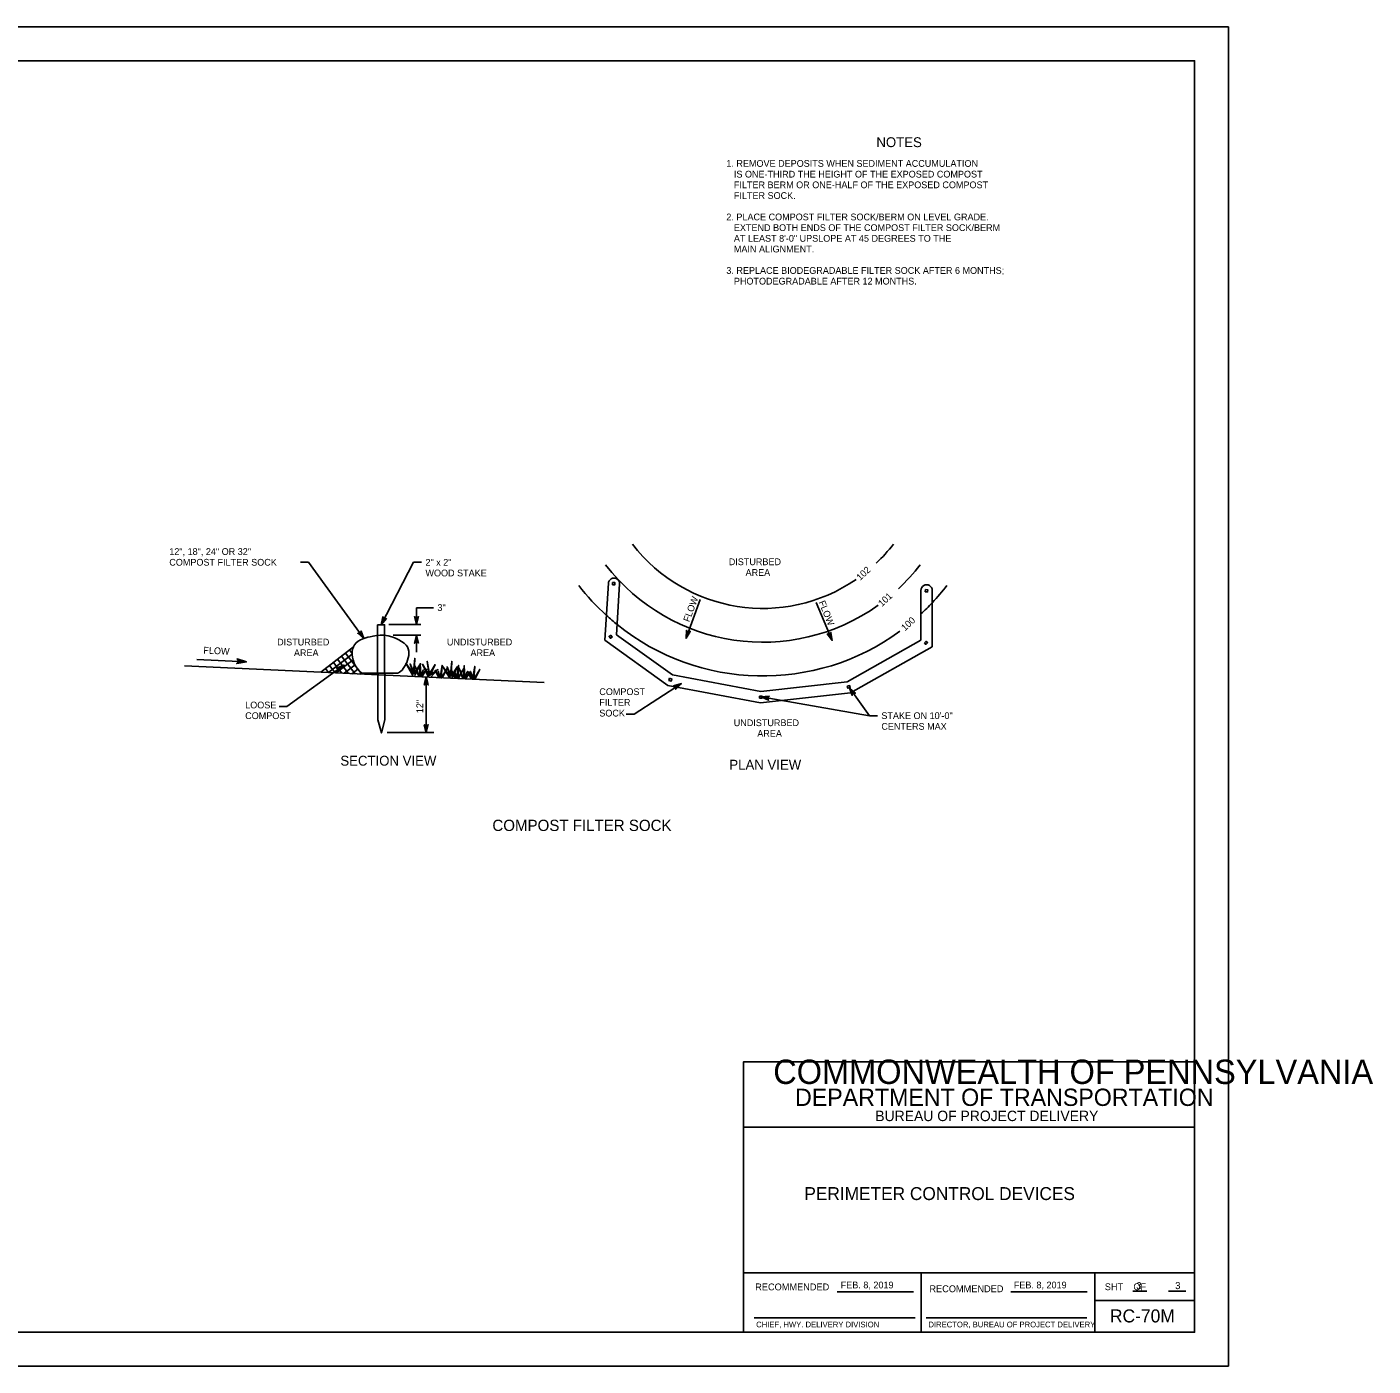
# Model space of a CAD drawing. Extents: x 636462 to 639049, y 299944 to 300538.
# Drawn here: x 638452 to 639049, y 299944 to 300538 of the extents above; entities that cross this region are included whole.
import ezdxf

# ---------------------------------------------------------------- set-up
doc = ezdxf.new("R2010")
doc.units = 0
for name, color, linetype in [('1', 7, 'Continuous'), ('Default', 7, 'Continuous'), ('PLT-BNDY', 7, 'Continuous')]:
    doc.layers.add(name, color=color, linetype=linetype)

msp = doc.modelspace()

# ---------------------------------------------------------------- linework, layer by layer
at = {"layer": '1'}
for p, q in [((638811.38, 299977.44), (638845.27, 299977.44)), ((638888.38, 299977.44), (638922.25, 299977.44)), ((638942.54, 299977.66), (638948.68, 299977.66)), ((638958.35, 299977.66), (638965.99, 299977.66)), ((638774.68, 299965.87), (638845.93, 299965.87)), ((638850.85, 299965.87), (638922.19, 299965.87))]:
    msp.add_line(p, q, dxfattribs=at)
msp.add_lwpolyline([(638969.91, 299959.45), (638969.91, 300523.45), (638183.91, 300523.45), (638183.91, 299959.45), (638969.91, 299959.45), (638969.91, 299985.81), (638769.91, 299985.81), (638769.91, 300050.49), (638969.91, 300050.49), (638969.91, 300079.45), (638769.91, 300079.45), (638769.91, 299959.45), (638848.72, 299959.45), (638848.72, 299985.81), (638848.72, 299959.45), (638925.72, 299959.45), (638925.72, 299985.81), (638925.72, 299973.49), (638969.91, 299973.49)], dxfattribs=at)
at = {"layer": 'Default'}
for p, q in [((638573.46, 300301.02), (638576.96, 300301.02)), ((638601.59, 300267.12), (638576.96, 300301.02)), ((638609.18, 300273.31), (638623.61, 300300.97)), ((638627.11, 300300.97), (638623.61, 300300.97)), ((638708.43, 300266.42), (638709.98, 300291.78)), ((638713.58, 300268.87), (638714.97, 300291.47)), ((638848.57, 300266.44), (638848.57, 300288.49)), ((638853.56, 300263.52), (638853.56, 300288.49)), ((638624.93, 300280.74), (638632.47, 300280.74)), ((638624.93, 300273.37), (638624.93, 300280.74)), ((638744.39, 300267.26), (638750.68, 300284.41)), ((638809.2, 300266.31), (638802.08, 300283.14)), ((638624.93, 300268.6), (638624.93, 300261.14)), ((638596.9, 300263.45), (638582.41, 300252.21)), ((638549.44, 300256.82), (638527.54, 300257.83)), ((638596.41, 300260.22), (638585.88, 300252.05)), ((638588.05, 300256.58), (638591.77, 300251.78)), ((638596.82, 300257.69), (638589.34, 300251.89)), ((638589.82, 300257.96), (638594.72, 300251.65)), ((638591.6, 300259.33), (638597.67, 300251.51)), ((638593.38, 300260.71), (638600.62, 300251.37)), ((638595.15, 300262.09), (638596.42, 300260.46)), ((638592.7, 300255.42), (638567.45, 300236.99)), ((638582.72, 300252.45), (638582.92, 300252.19)), ((638584.49, 300253.82), (638585.87, 300252.05)), ((638586.27, 300255.2), (638588.82, 300251.92)), ((638597.64, 300255.48), (638592.81, 300251.73)), ((638598.82, 300253.56), (638596.27, 300251.57)), ((638600.51, 300252.01), (638599.73, 300251.42)), ((638629.2, 300250.06), (638629.2, 300225.46)), ((638742.33, 300247.21), (638721.38, 300233.63)), ((638816.86, 300245.33), (638825.78, 300232.94)), ((638777.74, 300241.26), (638825.78, 300232.94)), ((638563.95, 300236.99), (638567.45, 300236.99)), ((638717.88, 300233.63), (638721.38, 300233.63)), ((638829.27, 300232.94), (638825.78, 300232.94))]:
    msp.add_line(p, q, dxfattribs=at)
for points in [[(638711.84, 300292), (638712.9, 300291.96), (638712.87, 300291.02), (638711.81, 300291.05)], [(638850.51, 300288.84), (638851.56, 300288.81), (638851.53, 300287.86), (638850.48, 300287.9)], [(638711.04, 300268.68), (638711.66, 300267.83), (638710.89, 300267.27), (638710.27, 300268.13)], [(638850.08, 300265.28), (638850.87, 300265.99), (638851.5, 300265.29), (638850.72, 300264.58)], [(638737.12, 300249.51), (638738.13, 300249.18), (638737.83, 300248.29), (638736.83, 300248.61)], [(638815.9, 300245.98), (638816.9, 300246.31), (638817.2, 300245.41), (638816.21, 300245.08)], [(638777.03, 300241.66), (638778.08, 300241.64), (638778.06, 300240.7), (638777.01, 300240.72)]]:
    msp.add_lwpolyline(points, close=True, dxfattribs=at)
for points in [[(638611.21, 300275.9), (638611.53, 300276.04), (638609.18, 300273.31), (638611.21, 300275.9), (638610.79, 300275.9), (638609.18, 300273.31), (638610.32, 300276.13), (638610.07, 300276.46), (638609.18, 300273.31), (638609.97, 300276.83), (638610.07, 300276.46)], [(638625.56, 300276.6), (638625.79, 300276.87), (638624.93, 300273.37), (638625.56, 300276.6), (638625.19, 300276.41), (638624.93, 300273.37), (638624.67, 300276.4), (638624.29, 300276.58), (638624.93, 300273.37), (638624.04, 300276.87), (638624.29, 300276.58)], [(638600.1, 300266.54), (638600.83, 300266.82), (638601.59, 300267.12), (638602.42, 300267.41), (638603.36, 300267.7), (638604.42, 300267.98), (638605.65, 300268.24), (638607.09, 300268.46), (638608.76, 300268.65), (638608.76, 300268.65), (638610.52, 300268.61), (638612.26, 300268.35), (638613.94, 300267.91), (638615.53, 300267.33), (638616.99, 300266.63), (638618.29, 300265.86), (638619.39, 300265.04), (638620.25, 300264.23), (638620.25, 300264.23), (638620.83, 300263.43), (638621.23, 300262.54), (638621.44, 300261.59), (638621.5, 300260.59), (638621.43, 300259.57), (638621.23, 300258.54), (638620.93, 300257.51), (638620.54, 300256.52), (638620.09, 300255.58), (638619.58, 300254.69), (638619.04, 300253.9), (638618.5, 300253.2), (638617.95, 300252.63), (638617.42, 300252.2), (638616.93, 300251.92), (638616.5, 300251.82), (638616.5, 300251.82), (638600.82, 300251.82), (638600.82, 300251.82), (638600.1, 300252.26), (638599.4, 300252.88), (638598.74, 300253.65), (638598.14, 300254.55), (638597.6, 300255.56), (638597.15, 300256.63), (638596.79, 300257.77), (638596.54, 300258.94), (638596.41, 300260.11), (638596.42, 300261.27), (638596.58, 300262.39), (638596.9, 300263.45), (638597.4, 300264.41), (638598.09, 300265.26), (638598.99, 300265.98), (638600.1, 300266.54)], [(638600.26, 300270.13), (638600.29, 300270.48), (638601.59, 300267.12), (638600.26, 300270.13), (638600.07, 300269.75), (638601.59, 300267.12), (638599.64, 300269.45), (638599.23, 300269.38), (638601.59, 300267.12), (638598.86, 300269.47), (638599.23, 300269.38)], [(638607.62, 300273.31), (638610.75, 300273.31), (638610.84, 300231.03), (638609.3, 300225.31), (638607.72, 300231.03), (638607.62, 300273.31)], [(638612.61, 300273.37), (638626.78, 300273.37)], [(638614.49, 300268.59), (638626.78, 300268.59)], [(638624.29, 300265.37), (638624.07, 300265.1), (638624.93, 300268.6), (638624.29, 300265.37), (638624.66, 300265.57), (638624.93, 300268.6), (638625.19, 300265.57), (638625.56, 300265.39), (638624.93, 300268.6), (638625.81, 300265.11), (638625.56, 300265.39)], [(638713.58, 300268.87), (638738.38, 300251.09), (638777.59, 300243.68), (638815.83, 300247.97), (638848.57, 300266.44)], [(638746.01, 300270.13), (638746.3, 300270.32), (638744.39, 300267.26), (638746.01, 300270.13), (638745.59, 300270.06), (638744.39, 300267.26), (638745.09, 300270.22), (638744.79, 300270.51), (638744.39, 300267.26), (638744.64, 300270.85), (638744.79, 300270.51)], [(638808.54, 300269.54), (638808.64, 300269.88), (638809.2, 300266.31), (638808.54, 300269.54), (638808.27, 300269.22), (638809.2, 300266.31), (638807.79, 300269.01), (638807.37, 300269.03), (638809.2, 300266.31), (638807.03, 300269.2), (638807.37, 300269.03)], [(638708.43, 300266.42), (638736.37, 300246.38), (638777.4, 300238.64), (638817.4, 300243.12), (638853.56, 300263.52)], [(638545.62, 300257.85), (638545.31, 300258.14), (638549.44, 300256.82), (638545.62, 300257.85), (638545.82, 300257.38), (638549.44, 300256.82), (638545.79, 300256.76), (638545.54, 300256.32), (638549.44, 300256.82), (638545.18, 300256.04), (638545.54, 300256.32)], [(638624.21, 300250.74), (638626.73, 300255.99), (638623.89, 300251.78), (638624.1, 300258.41), (638623.54, 300252.33), (638622.04, 300255.92), (638623.5, 300251.46), (638620.1, 300256.19), (638623.25, 300250.8)], [(638631.15, 300249.91), (638634.36, 300253.42), (638630.93, 300250.98), (638633.1, 300255.6), (638630.64, 300251.56), (638629.68, 300257.09), (638630.51, 300250.7), (638627.58, 300255.73), (638630.2, 300250.07)], [(638640.6, 300249.45), (638643.13, 300254.69), (638640.29, 300250.49), (638640.49, 300257.12), (638639.94, 300251.04), (638638.44, 300254.63), (638639.89, 300250.17), (638636.49, 300254.9), (638639.65, 300249.51)], [(638521.95, 300254.99), (638681.43, 300247.66)], [(638589.73, 300254), (638589.38, 300254.02), (638592.7, 300255.42), (638589.73, 300254), (638590.11, 300253.82), (638592.7, 300255.42), (638590.42, 300253.4), (638590.5, 300252.99), (638592.7, 300255.42), (638590.43, 300252.62), (638590.5, 300252.99)], [(638625.89, 300250.36), (638624.14, 300255), (638626.26, 300250.4), (638626.56, 300256.05), (638626.79, 300250.4), (638627.9, 300253.18), (638627.03, 300250.44), (638629.35, 300253.45), (638627.27, 300250.23)], [(638636.27, 300249.69), (638638.52, 300253.94), (638635.84, 300249.65), (638636.26, 300255.29), (638635.32, 300249.72), (638634.57, 300252.62), (638635.08, 300249.78), (638633.17, 300253.07), (638634.74, 300249.76)], [(638643.58, 300249.62), (638645.84, 300253.88), (638643.15, 300249.59), (638643.57, 300255.23), (638642.63, 300249.65), (638641.88, 300252.55), (638642.4, 300249.72), (638640.48, 300253.01), (638642.06, 300249.7)], [(638645.39, 300249.5), (638643.63, 300254.14), (638645.75, 300249.55), (638646.05, 300255.19), (638646.28, 300249.54), (638647.39, 300252.32), (638646.52, 300249.58), (638648.84, 300252.6), (638646.76, 300249.37)], [(638650.71, 300249.19), (638652.96, 300253.45), (638650.27, 300249.16), (638650.7, 300254.8), (638649.75, 300249.22), (638649.01, 300252.12), (638649.52, 300249.29), (638647.6, 300252.58), (638649.18, 300249.27)], [(638628.56, 300246.83), (638628.34, 300246.56), (638629.2, 300250.06), (638628.56, 300246.83), (638628.93, 300247.03), (638629.2, 300250.06), (638629.46, 300247.03), (638629.83, 300246.85), (638629.2, 300250.06), (638630.08, 300246.57), (638629.83, 300246.85)], [(638739.24, 300246.08), (638738.9, 300246.13), (638742.33, 300247.21), (638739.24, 300246.08), (638739.6, 300245.86), (638742.33, 300247.21), (638739.88, 300245.42), (638739.92, 300245), (638742.33, 300247.21), (638739.81, 300244.64), (638739.92, 300245)], [(638818.13, 300242.29), (638818.09, 300241.94), (638816.86, 300245.33), (638818.13, 300242.29), (638818.33, 300242.66), (638816.86, 300245.33), (638818.76, 300242.96), (638819.17, 300243.02), (638816.86, 300245.33), (638819.54, 300242.92), (638819.17, 300243.02)], [(638780.81, 300240.08), (638781.04, 300239.81), (638777.74, 300241.26), (638780.81, 300240.08), (638780.68, 300240.48), (638777.74, 300241.26), (638780.77, 300241), (638781.01, 300241.34), (638777.74, 300241.26), (638781.33, 300241.54), (638781.01, 300241.34)], [(638629.83, 300228.69), (638630.06, 300228.96), (638629.2, 300225.46), (638629.83, 300228.69), (638629.46, 300228.49), (638629.2, 300225.46), (638628.94, 300228.49), (638628.56, 300228.67), (638629.2, 300225.46), (638628.31, 300228.95), (638628.56, 300228.67)], [(638611.86, 300225.46), (638632.64, 300225.46)]]:
    msp.add_lwpolyline(points, dxfattribs=at)
for centre, radius, start, end in [((638778.47, 300353.57), 73.04, 217.62146, 304.47323), ((638778.47, 300353.57), 73.04, 313.52077, 322.37854), ((638778.47, 300353.57), 88.03, 217.62146, 305.53768), ((638778.47, 300353.57), 88.03, 313.0326, 322.37854), ((638712.47, 300291.47), 2.5, 359.99938, 180.00062), ((638778.47, 300353.57), 103.02, 217.62146, 227.67001), ((638851.07, 300288.49), 2.5, 359.99938, 180.00062), ((638778.47, 300353.57), 103.02, 316.79278, 322.37854), ((638778.47, 300353.57), 103.02, 312.87336, 316.79278), ((638778.47, 300353.57), 103.02, 227.67001, 231.15361), ((638778.47, 300353.57), 103.02, 231.15361, 306.13463)]:
    msp.add_arc(centre, radius, start, end, dxfattribs=at)
at = {"layer": 'PLT-BNDY'}
msp.add_lwpolyline([(638143.91, 300538.45), (638984.91, 300538.45), (638984.91, 299944.45), (638143.91, 299944.45)], close=True, dxfattribs=at)

# ---------------------------------------------------------------- texts
at = {"layer": '1'}
for s, height, p in [('COMMONWEALTH OF PENNSYLVANIA', 10.7834, (638783.07, 300069.59)), ('DEPARTMENT OF TRANSPORTATION', 7.6843, (638792.75, 300059.84)), ('BUREAU OF PROJECT DELIVERY', 4.6221, (638828.32, 300053.11)), ('RECOMMENDED', 3.048, (638775.08, 299978.04)), ('APPROVED', 0.0192, (638812.94, 299977.38)), ('APPROVED', 0.0192, (638812.94, 299977.38)), ('APPROVED', 0.0192, (638812.94, 299977.38)), ('APPROVED', 0.0192, (638812.94, 299977.38)), ('FEB. 8, 2019', 3, (638812.99, 299978.92)), ('RECOMMENDED', 3.048, (638852.32, 299977.21)), ('FEB. 8, 2019', 3, (638889.74, 299978.92)), ('SHT    OF', 3.048, (638930.08, 299978.12)), ('3', 3.13, (638944.05, 299978.54)), ('3', 3.13, (638961.28, 299978.59)), ('CHIEF, HWY. DELIVERY DIVISION', 2.54, (638775.5, 299961.62)), ('DIRECTOR, BUREAU OF PROJECT DELIVERY', 2.54, (638851.88, 299961.62))]:
    msp.add_text(s, height=height, dxfattribs=at).set_placement(p)
at = {"layer": 'Default'}
for s, height, p in [('NOTES', 4.372, (638828.81, 300485.13)), ('   AT LEAST 8\'-0" UPSLOPE AT 45 DEGREES TO THE', 2.998, (638762.28, 300443.16)), ('12", 18", 24" OR 32"', 2.998, (638515.28, 300304.24)), ('COMPOST FILTER SOCK', 2.998, (638515.28, 300299.49)), ('2" x 2" ', 2.998, (638628.86, 300299.47)), ('DISTURBED', 2.998, (638763.35, 300299.7)), ('WOOD STAKE', 2.998, (638628.86, 300294.73)), ('AREA', 2.998, (638770.8, 300294.95)), ('3"', 2.998, (638634.16, 300279.38)), ('DISTURBED', 2.998, (638563.09, 300264.09)), ('UNDISTURBED', 2.998, (638638.38, 300264.09)), ('AREA', 2.998, (638570.54, 300259.34)), ('AREA', 2.998, (638648.83, 300259.34)), ('COMPOST', 2.998, (638705.95, 300242.08)), ('LOOSE ', 2.998, (638548.93, 300236.17)), ('FILTER', 2.998, (638705.95, 300237.33)), ('COMPOST', 2.998, (638548.93, 300231.43)), ('SOCK', 2.998, (638705.95, 300232.58)), ('STAKE ON 10\'-0"', 2.998, (638831.02, 300231.44)), ('UNDISTURBED', 2.998, (638765.55, 300228.3)), ('CENTERS MAX ', 2.998, (638831.02, 300226.69)), ('AREA', 2.998, (638776, 300223.56)), ('SECTION VIEW', 4.3721, (638591.14, 300210.78)), ('PLAN VIEW', 4.372, (638763.62, 300209.01)), ('COMPOST FILTER SOCK', 4.9967, (638658.54, 300181.79)), ('PERIMETER CONTROL DEVICES', 5.7257, (638796.87, 300018.1)), ('RC-70M', 5.779, (638932.37, 299963.81))]:
    msp.add_text(s, height=height, dxfattribs=at).set_placement(p)
for s, rotation, p in [('1. REMOVE DEPOSITS WHEN SEDIMENT ACCUMULATION', 360, (638762.28, 300476.39)), ('   IS ONE-THIRD THE HEIGHT OF THE EXPOSED COMPOST ', 360, (638762.28, 300471.64)), ('   FILTER BERM OR ONE-HALF OF THE EXPOSED COMPOST', 360, (638762.28, 300466.9)), ('   FILTER SOCK.', 360, (638762.28, 300462.15)), ('2. PLACE COMPOST FILTER SOCK/BERM ON LEVEL GRADE.', 360, (638762.28, 300452.66)), ('   EXTEND BOTH ENDS OF THE COMPOST FILTER SOCK/BERM', 360, (638762.28, 300447.91)), ('   MAIN ALIGNMENT.', 360, (638762.28, 300438.42)), ('3. REPLACE BIODEGRADABLE FILTER SOCK AFTER 6 MONTHS; ', 360, (638762.28, 300428.92)), ('   PHOTODEGRADABLE AFTER 12 MONTHS.', 360, (638762.28, 300424.18)), ('102', 43.15239, (638821.61, 300292.69)), ('101', 43.15239, (638831.27, 300281.08)), ('FLOW', 69.55071, (638745.86, 300274.26)), ('FLOW', 291.98244, (638803.15, 300283.29)), ('100', 43.15239, (638841.48, 300270.3)), ('FLOW', 357.06624, (638530.34, 300260.53)), ('12"', 90, (638627.85, 300234.05))]:
    msp.add_text(s, height=2.998, rotation=rotation, dxfattribs=at).set_placement(p)

doc.saveas('drawing.dxf')
